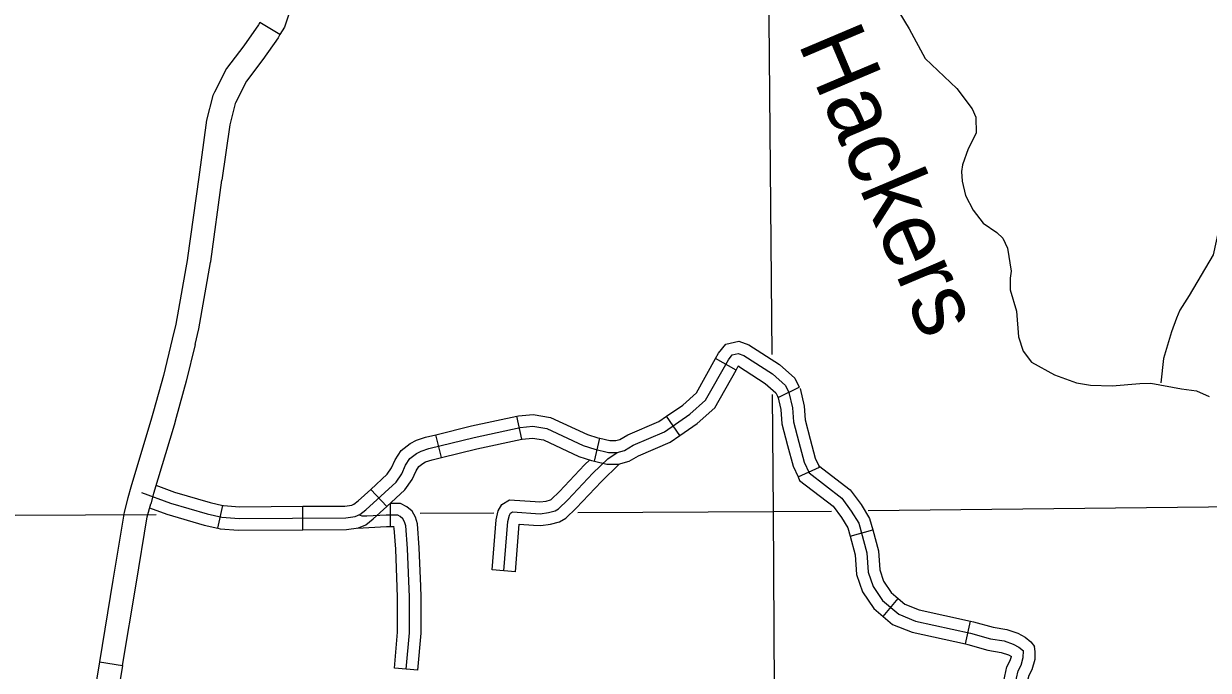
# Model space of a CAD drawing. Extents: x 1373862 to 1376999, y 1168398 to 1170455.
# Drawn here: x 1375258.9 to 1375410.3, y 1168667 to 1168749.6 of the extents above; entities that cross this region are included whole.
import ezdxf

# ---------------------------------------------------------------- set-up
doc = ezdxf.new("R2010")
doc.units = 0
for name, color, linetype in [('Level 31', 7, 'Continuous'), ('Level 32', 7, 'Continuous'), ('Level 35', 7, 'Continuous'), ('Level 45', 7, 'Continuous'), ('Level 5', 7, 'Continuous')]:
    doc.layers.add(name, color=color, linetype=linetype)

msp = doc.modelspace()

# ---------------------------------------------------------------- linework, layer by layer
at = {"layer": 'Level 31'}
for p, q in [((1375291.68, 1168748.23), (1375289.12, 1168749.79)), ((1375282.8, 1168719.1), (1375282.8, 1168719.1)), ((1375268.62, 1168668.08), (1375271.58, 1168667.6))]:
    msp.add_line(p, q, dxfattribs=at)
for points in [[(1375295.2, 1168758.55), (1375293.39, 1168752.71), (1375292.25, 1168749.16), (1375291.68, 1168748.23)], [(1375289.12, 1168749.79), (1375288.93, 1168749.47), (1375287.08, 1168746.81), (1375284.84, 1168743.9), (1375283.32, 1168740.86)], [(1375291.68, 1168748.23), (1375291.44, 1168747.83), (1375289.51, 1168745.04), (1375287.4, 1168742.3), (1375286, 1168739.51)], [(1375283.32, 1168740.86), (1375283.12, 1168740.46), (1375282.31, 1168737.28), (1375281.3, 1168730.02)], [(1375286, 1168739.51), (1375285.95, 1168739.41), (1375285.26, 1168736.71), (1375284.27, 1168729.61)], [(1375281.3, 1168730.02), (1375279.86, 1168719.69), (1375279.85, 1168719.62)], [(1375282.8, 1168719.1), (1375282.83, 1168719.22), (1375284.27, 1168729.61)], [(1375279.85, 1168719.62), (1375278.36, 1168711.24), (1375277.91, 1168709.33)], [(1375280.83, 1168708.64), (1375281.3, 1168710.62), (1375282.8, 1168719.1)], [(1375277.91, 1168709.33), (1375276.8, 1168704.67), (1375275.54, 1168700.12), (1375275.26, 1168699.2)], [(1375280.83, 1168708.64), (1375279.7, 1168703.93), (1375278.42, 1168699.29), (1375278.14, 1168698.34)], [(1375275.26, 1168699.2), (1375272.61, 1168690.38), (1375272.26, 1168689.02)], [(1375278.14, 1168698.34), (1375275.5, 1168689.57), (1375275.16, 1168688.26)], [(1375272.26, 1168689.02), (1375271.78, 1168687.22), (1375270.34, 1168678.5)], [(1375273.3, 1168678.01), (1375274.72, 1168686.59), (1375275.16, 1168688.26)], [(1375270.34, 1168678.5), (1375268.62, 1168668.08)], [(1375271.58, 1168667.6), (1375273.3, 1168678.01)], [(1375268.62, 1168668.08), (1375266.9, 1168657.67)], [(1375271.58, 1168667.6), (1375269.86, 1168657.18)]]:
    msp.add_lwpolyline(points, dxfattribs=at)
at = {"layer": 'Level 32'}
for p, q in [((1375349.96, 1168705.37), (1375347.34, 1168706.83)), ((1375355.36, 1168701.85), (1375358.04, 1168703.19)), ((1375322.57, 1168696.53), (1375321.94, 1168699.47)), ((1375342.79, 1168696.99), (1375341.08, 1168699.46)), ((1375312.32, 1168694.19), (1375311.6, 1168697.1)), ((1375331.87, 1168693.73), (1375332.57, 1168696.64)), ((1375357.88, 1168691.7), (1375360.61, 1168692.95)), ((1375305.33, 1168687.92), (1375303.3, 1168690.12)), ((1375283.74, 1168685.14), (1375284.39, 1168688.07)), ((1375294.62, 1168684.95), (1375294.61, 1168687.95)), ((1375364.54, 1168684.15), (1375367.43, 1168684.94)), ((1375368.74, 1168673.89), (1375370.67, 1168676.19)), ((1375379.3, 1168670.36), (1375379.94, 1168673.29))]:
    msp.add_line(p, q, dxfattribs=at)
for points in [[(1375347.34, 1168706.83), (1375347.73, 1168707.54), (1375348.64, 1168708.67), (1375350.32, 1168709.04), (1375351.6, 1168708.59), (1375355.5, 1168706.06), (1375357.47, 1168704.34), (1375358.04, 1168703.19)], [(1375273.99, 1168689.73), (1375277.71, 1168688.35), (1375282.37, 1168686.98), (1375284.24, 1168686.56), (1375286.45, 1168686.4), (1375300.08, 1168686.48), (1375301.29, 1168686.65), (1375301.88, 1168686.91), (1375302.65, 1168687.49), (1375306.52, 1168691.04), (1375307.26, 1168692.11), (1375307.74, 1168693.19), (1375308.28, 1168694.06), (1375309.12, 1168694.72), (1375309.71, 1168695.01), (1375310.7, 1168695.34), (1375316.48, 1168696.75), (1375322.39, 1168698.03), (1375324, 1168698.18), (1375325.8, 1168697.88), (1375330.43, 1168695.73), (1375331.9, 1168695.26), (1375333.65, 1168694.84), (1375334.77, 1168694.84), (1375335.72, 1168695.09), (1375336.81, 1168695.76), (1375340.83, 1168697.46), (1375344.07, 1168699.71), (1375346.07, 1168701.5), (1375348.98, 1168706.69), (1375349.48, 1168707.32), (1375350.23, 1168707.49), (1375350.94, 1168707.24), (1375354.6, 1168704.86), (1375356.26, 1168703.41), (1375356.72, 1168702.49), (1375357.17, 1168700.54), (1375357.3, 1168698.75), (1375358, 1168696.13), (1375358.67, 1168693.59), (1375359.29, 1168692.22), (1375363.48, 1168689.01), (1375364.68, 1168687.34), (1375365.64, 1168685.81), (1375366.68, 1168682.02), (1375366.84, 1168679.52), (1375367.47, 1168677.69), (1375368.67, 1168675.91), (1375370.75, 1168674.16), (1375372.91, 1168673.29), (1375379.93, 1168671.76), (1375382.49, 1168671.03), (1375384.21, 1168670.74), (1375385.35, 1168670.34), (1375386.08, 1168669.97), (1375386.71, 1168669.47)], [(1375341.08, 1168699.46), (1375343.14, 1168700.89), (1375344.89, 1168702.45), (1375347.34, 1168706.83)], [(1375349.96, 1168705.37), (1375350.23, 1168705.85), (1375350.26, 1168705.89), (1375350.27, 1168705.88), (1375353.69, 1168703.66), (1375355.05, 1168702.47), (1375355.36, 1168701.85)], [(1375342.79, 1168696.99), (1375345, 1168698.53), (1375347.26, 1168700.54), (1375349.96, 1168705.37)], [(1375358.14, 1168703.01), (1375358.66, 1168700.76), (1375358.78, 1168699), (1375359.45, 1168696.52), (1375360.09, 1168694.1), (1375360.61, 1168692.95)], [(1375355.36, 1168701.85), (1375355.3, 1168701.98), (1375355.68, 1168700.31), (1375355.81, 1168698.5), (1375356.55, 1168695.74), (1375357.25, 1168693.09), (1375357.88, 1168691.7)], [(1375311.6, 1168697.1), (1375316.15, 1168698.22), (1375321.94, 1168699.47)], [(1375321.94, 1168699.47), (1375322.15, 1168699.51), (1375324.05, 1168699.7), (1375326.25, 1168699.32), (1375330.97, 1168697.13), (1375332.3, 1168696.71), (1375332.57, 1168696.64)], [(1375332.57, 1168696.64), (1375333.82, 1168696.34), (1375334.58, 1168696.34), (1375335.13, 1168696.48), (1375336.12, 1168697.09), (1375340.1, 1168698.78), (1375341.08, 1168699.46)], [(1375303.3, 1168690.12), (1375305.38, 1168692.04), (1375305.95, 1168692.85), (1375306.41, 1168693.89), (1375307.15, 1168695.08), (1375308.32, 1168695.99), (1375309.13, 1168696.4), (1375310.29, 1168696.78), (1375311.6, 1168697.1)], [(1375331.87, 1168693.73), (1375333.47, 1168693.34), (1375334.96, 1168693.34), (1375336.32, 1168693.7), (1375337.5, 1168694.42), (1375341.56, 1168696.14), (1375342.79, 1168696.99)], [(1375312.32, 1168694.19), (1375316.82, 1168695.29), (1375322.57, 1168696.53)], [(1375322.57, 1168696.53), (1375322.62, 1168696.54), (1375323.94, 1168696.67), (1375325.35, 1168696.43), (1375329.88, 1168694.33), (1375331.49, 1168693.82), (1375331.87, 1168693.73)], [(1375305.33, 1168687.92), (1375307.65, 1168690.05), (1375308.58, 1168691.36), (1375309.07, 1168692.49), (1375309.42, 1168693.04), (1375309.93, 1168693.44), (1375310.28, 1168693.62), (1375311.12, 1168693.9), (1375312.32, 1168694.19)], [(1375360.5, 1168693.18), (1375364.56, 1168690.07), (1375365.93, 1168688.18), (1375367.03, 1168686.41), (1375367.43, 1168684.94)], [(1375275.83, 1168690.65), (1375278.19, 1168689.78), (1375282.75, 1168688.43), (1375284.39, 1168688.07)], [(1375357.88, 1168691.7), (1375358.08, 1168691.26), (1375362.39, 1168687.95), (1375363.43, 1168686.51), (1375364.25, 1168685.2), (1375364.54, 1168684.15)], [(1375294.61, 1168687.95), (1375299.97, 1168687.98), (1375300.88, 1168688.1), (1375301.12, 1168688.21), (1375301.69, 1168688.64), (1375303.3, 1168690.12)], [(1375275.02, 1168687.75), (1375277.24, 1168686.93), (1375282, 1168685.53), (1375283.74, 1168685.14)], [(1375284.39, 1168688.07), (1375284.46, 1168688.05), (1375286.5, 1168687.9), (1375294.61, 1168687.95)], [(1375294.62, 1168684.95), (1375300.19, 1168684.98), (1375301.7, 1168685.19), (1375302.64, 1168685.6), (1375303.61, 1168686.34), (1375305.33, 1168687.92)], [(1375283.74, 1168685.14), (1375284.02, 1168685.08), (1375286.39, 1168684.9), (1375294.62, 1168684.95)], [(1375367.43, 1168684.94), (1375368.16, 1168682.27), (1375368.33, 1168679.82), (1375368.82, 1168678.37), (1375369.8, 1168676.92), (1375370.67, 1168676.19)], [(1375364.54, 1168684.15), (1375365.19, 1168681.77), (1375365.36, 1168679.23), (1375366.11, 1168677.02), (1375367.55, 1168674.89), (1375368.74, 1168673.89)], [(1375370.67, 1168676.19), (1375371.53, 1168675.46), (1375373.36, 1168674.72), (1375379.94, 1168673.29)], [(1375368.74, 1168673.89), (1375369.97, 1168672.86), (1375372.47, 1168671.85), (1375379.3, 1168670.36)], [(1375379.94, 1168673.29), (1375380.29, 1168673.21), (1375382.82, 1168672.49), (1375384.58, 1168672.2), (1375385.95, 1168671.73), (1375386.9, 1168671.23), (1375387.64, 1168670.64), (1375388.08, 1168670.02)], [(1375379.3, 1168670.36), (1375379.56, 1168670.3), (1375382.15, 1168669.56), (1375383.84, 1168669.28), (1375384.76, 1168668.96), (1375385.15, 1168668.76)], [(1375387.22, 1168665.44), (1375387.26, 1168665.74), (1375387.41, 1168666.39), (1375387.78, 1168667.1), (1375388.17, 1168668.4), (1375388.2, 1168669.41), (1375388.08, 1168670.02)], [(1375384.24, 1168665.82), (1375384.3, 1168666.26), (1375384.57, 1168667.45), (1375384.99, 1168668.24), (1375385.15, 1168668.76)]]:
    msp.add_lwpolyline(points, dxfattribs=at)
at = {"layer": 'Level 35'}
for points in [[(1375370.75, 1168751.16), (1375372.08, 1168748.96), (1375374.13, 1168745.18), (1375378.16, 1168741.33), (1375380.12, 1168738.76), (1375380.58, 1168737.68), (1375380.63, 1168735.62), (1375379.62, 1168733.65), (1375378.89, 1168731.57), (1375378.79, 1168730.73), (1375378.84, 1168729.51), (1375379.3, 1168727.69), (1375380.26, 1168725.81), (1375381.52, 1168724.12), (1375383.29, 1168722.92), (1375384.03, 1168722.22), (1375384.66, 1168720.93), (1375385.13, 1168718), (1375384.99, 1168717.11), (1375384.98, 1168715.63), (1375385.79, 1168712.88), (1375386.05, 1168709.62), (1375386.63, 1168707.79), (1375387.72, 1168706.35), (1375390.64, 1168704.74), (1375393.48, 1168703.75), (1375395.26, 1168703.45), (1375398.04, 1168703.36), (1375401.55, 1168703.66), (1375402.97, 1168703.69), (1375406.9, 1168702.95), (1375408.81, 1168702.69), (1375410.41, 1168701.97)], [(1375429.44, 1168744.16), (1375426.92, 1168742.6), (1375426.48, 1168741.97), (1375425.22, 1168739.51), (1375423.73, 1168738.23), (1375420.01, 1168738.21), (1375419.14, 1168737.88), (1375416.54, 1168736.2), (1375415.68, 1168734.84), (1375414.7, 1168732.95), (1375412.25, 1168726.92), (1375411.62, 1168723.18), (1375410.93, 1168720.09), (1375407.86, 1168714.87), (1375406.65, 1168713.02), (1375406.23, 1168712.01), (1375405.59, 1168710.25), (1375404.57, 1168706.84), (1375404.24, 1168703.72)]]:
    msp.add_lwpolyline(points, dxfattribs=at)
at = {"layer": 'Level 45'}
for p, q in [((1375305.75, 1168688.31), (1375305.75, 1168685.31)), ((1375321.79, 1168679.58), (1375318.8, 1168679.82)), ((1375309.3, 1168667.01), (1375306.31, 1168667.27))]:
    msp.add_line(p, q, dxfattribs=at)
for points in [[(1375320.3, 1168679.7), (1375320.78, 1168685.99), (1375320.99, 1168686.82), (1375321.14, 1168687.09), (1375321.39, 1168687.24), (1375324.94, 1168687.01), (1375325.98, 1168687.16), (1375326.83, 1168687.36), (1375327.27, 1168687.63), (1375328.48, 1168688.78), (1375331.68, 1168692.19), (1375333.56, 1168694.01), (1375334.77, 1168694.84)], [(1375324.27, 1168688.56), (1375324.89, 1168688.52), (1375325.7, 1168688.63), (1375326.25, 1168688.76), (1375326.35, 1168688.83), (1375327.41, 1168689.84), (1375330.61, 1168693.24), (1375331.27, 1168693.89)], [(1375324.08, 1168685.56), (1375325, 1168685.5), (1375326.26, 1168685.68), (1375327.42, 1168685.96), (1375328.19, 1168686.44), (1375329.54, 1168687.72), (1375332.75, 1168691.14), (1375335.03, 1168693.34)], [(1375309.67, 1168677.74), (1375309.47, 1168682.66), (1375309.25, 1168685.72), (1375308.99, 1168686.57), (1375308.58, 1168687.31), (1375307.9, 1168687.9), (1375307.08, 1168688.31), (1375306.27, 1168688.31), (1375305.76, 1168688.31)], [(1375318.8, 1168679.82), (1375319.3, 1168686.23), (1375319.58, 1168687.37), (1375320.02, 1168688.18), (1375321.03, 1168688.76), (1375324.27, 1168688.56)], [(1375307.81, 1168667.14), (1375308.22, 1168671.8), (1375308.22, 1168676.33), (1375307.97, 1168682.57), (1375307.76, 1168685.44), (1375307.6, 1168685.98), (1375307.39, 1168686.36), (1375307.06, 1168686.65), (1375306.73, 1168686.81), (1375306.27, 1168686.81), (1375305.27, 1168686.81), (1375302.78, 1168686.69), (1375302.19, 1168686.69), (1375301.76, 1168686.85)], [(1375305.75, 1168685.31), (1375305.31, 1168685.31), (1375301.56, 1168685.13)], [(1375306.67, 1168677.62), (1375306.47, 1168682.49), (1375306.28, 1168685.16), (1375306.23, 1168685.31), (1375306.27, 1168685.31), (1375305.75, 1168685.31)], [(1375321.79, 1168679.58), (1375322.26, 1168685.68), (1375324.08, 1168685.56)], [(1375306.31, 1168667.27), (1375306.72, 1168671.86), (1375306.72, 1168676.3), (1375306.67, 1168677.62)], [(1375309.3, 1168667.01), (1375309.72, 1168671.73), (1375309.72, 1168676.36), (1375309.67, 1168677.74)], [(1375354.11, 1168639.25), (1375363.34, 1168643.51), (1375366.32, 1168645), (1375367.91, 1168646.64), (1375370.17, 1168649.78), (1375371.05, 1168650.84), (1375371.85, 1168651.64), (1375372.91, 1168652.52), (1375374.62, 1168653.18), (1375378.08, 1168656.5), (1375379.41, 1168657.74), (1375381.89, 1168660.29), (1375382.96, 1168661.29), (1375384.86, 1168663.68), (1375385.65, 1168664.94), (1375385.78, 1168666), (1375385.99, 1168666.92), (1375386.39, 1168667.67), (1375386.67, 1168668.64), (1375386.71, 1168669.47)]]:
    msp.add_lwpolyline(points, dxfattribs=at)
at = {"layer": 'Level 5'}
for points in [[(1375353.77, 1168793.03), (1375354.52, 1168707.34)], [(1375354.57, 1168702.23), (1375354.7, 1168687.27)], [(1375366.85, 1168687.4), (1375449.87, 1168688.3)], [(1375248.75, 1168686.79), (1375275.84, 1168686.92)], [(1375309.61, 1168687.07), (1375318.99, 1168687.11)], [(1375329.76, 1168687.16), (1375354.7, 1168687.27)], [(1375354.7, 1168687.27), (1375362.17, 1168687.35)], [(1375354.7, 1168687.27), (1375354.98, 1168641.87)]]:
    msp.add_lwpolyline(points, dxfattribs=at)

# ---------------------------------------------------------------- texts
at = {"layer": 'Level 35'}
msp.add_text('Hackers', height=8.448, rotation=292.9366, dxfattribs=at).set_placement((1375357.83, 1168747.15))

doc.saveas('drawing.dxf')
